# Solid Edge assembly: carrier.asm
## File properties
Title: Carrier Assembly
Subject: Trolley Wheel Assembly
Author: Dwight Yorke
Keywords: Subassembly
Comments: Carrier Subassembly
Template: metric.asm
Last saved by: rkriggs
Revision: 64
Application: Solid Edge
File Size: 0
Number of Sheets: 0
Number of Objects: 0
Document Number: CSA-101
Revision: 1
Project Name: Trolley Wheel Assembly
Category: Subassembly
Manager: Brian Little
Company: Wheels R Us
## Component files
chead.par
Splate.par
mtgpin.par
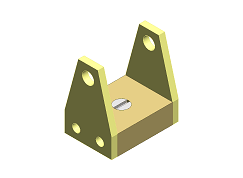
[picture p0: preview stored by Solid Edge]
